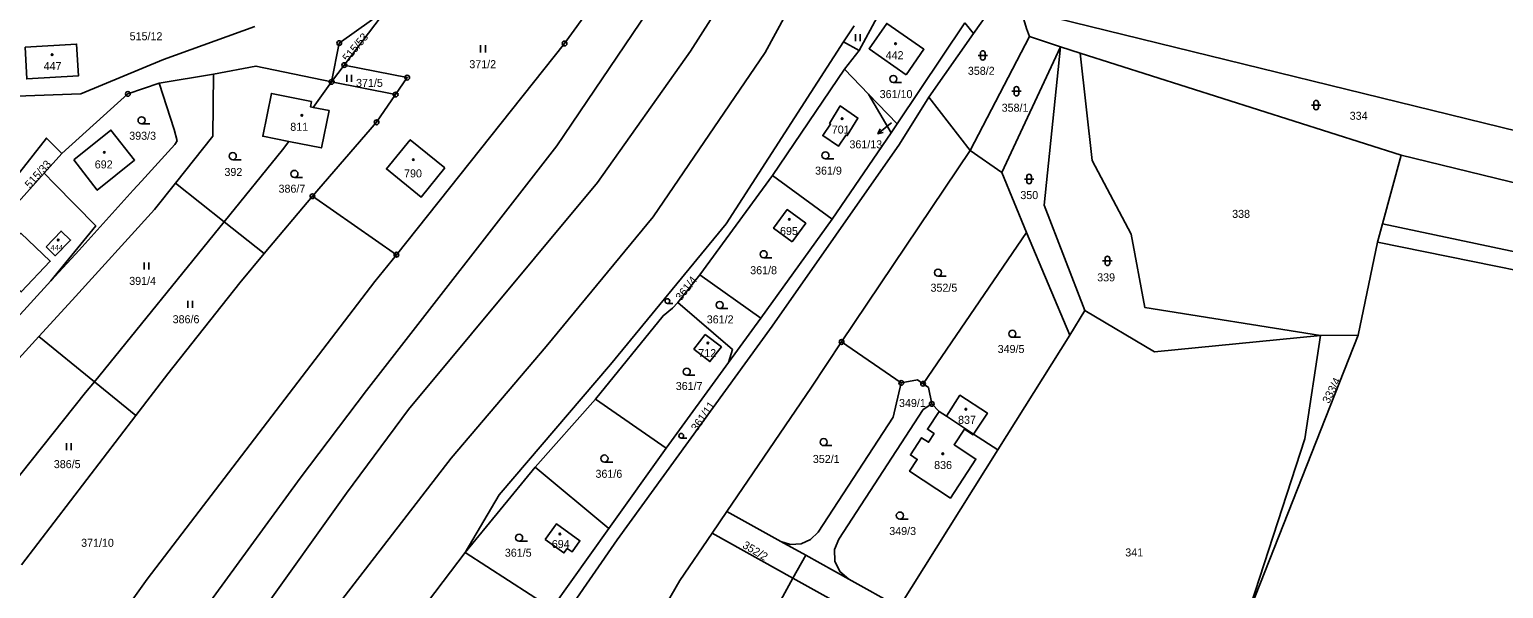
# Model space of a CAD drawing. Extents: x -725728 to -720881, y -1068679 to -1063504.
# Drawn here: x -722498.2 to -722185.2, y -1065489.8 to -1065371.2 of the extents above; entities that cross this region are included whole.
import ezdxf

# ---------------------------------------------------------------- set-up
doc = ezdxf.new("R2010")
doc.units = 0
for name, color, linetype in [('Hranice parcel', 7, 'Continuous'), ('Parcelní čísla', 7, 'Continuous'), ('Pop  PČ popisy', 7, 'Continuous'), ('Značky bodu BP', 7, 'Continuous'), ('Značky budov', 7, 'Continuous'), ('Značky kultur', 7, 'Continuous')]:
    doc.layers.add(name, color=color, linetype=linetype)

# ---------------------------------------------------------------- blocks, each defined once
blk = doc.blocks.new('4.02_4')
at = {"layer": 'Značky budov'}
blk.add_circle((-0.001, 0), 0.0175, dxfattribs=at)
blk = doc.blocks.new('4.02_3')
at = {"layer": 'Značky budov'}
blk.add_circle((-0.001, 0), 0.0175, dxfattribs=at)
blk = doc.blocks.new('1029_162')
at = {"layer": 'Pop  PČ popisy'}
for p, q in [((0, 0), (-0.233, -0.189)), ((-0.233, -0.189), (-0.187, -0.087)), ((-0.233, -0.189), (-0.124, -0.165))]:
    blk.add_line(p, q, dxfattribs=at)
blk = doc.blocks.new('3.04_2')
at = {"layer": 'Značky kultur'}
blk.add_line((0.001, 0), (0.176, 0), dxfattribs=at)
blk.add_circle((0.001, 0.075), 0.075, dxfattribs=at)
blk = doc.blocks.new('3.06_2')
at = {"layer": 'Značky kultur'}
for p, q in [((-0.051, 0), (-0.051, 0.15)), ((0.049, 0), (0.049, 0.15))]:
    blk.add_line(p, q, dxfattribs=at)
blk = doc.blocks.new('3.06_1')
at = {"layer": 'Značky kultur'}
for p, q in [((-0.051, 0), (-0.051, 0.15)), ((0.049, 0), (0.049, 0.15))]:
    blk.add_line(p, q, dxfattribs=at)
blk = doc.blocks.new('3.04_4')
at = {"layer": 'Značky kultur'}
blk.add_line((0, 0), (0.118, 0), dxfattribs=at)
blk.add_circle((0, 0.05), 0.0502, dxfattribs=at)
blk = doc.blocks.new('3.04_3')
at = {"layer": 'Značky kultur'}
blk.add_line((0.001, 0), (0.176, 0), dxfattribs=at)
blk.add_circle((0.001, 0.075), 0.075, dxfattribs=at)
blk = doc.blocks.new('3.16_2')
at = {"layer": 'Značky kultur'}
for p, q in [((-0.1, 0.1), (0.1, 0.1)), ((-0.05, 0.15), (-0.05, 0.05)), ((0.05, 0.05), (0.05, 0.15))]:
    blk.add_line(p, q, dxfattribs=at)
for centre, start, end in [((0, 0.15), 0, 180), ((0, 0.05), 180, 359.9879)]:
    blk.add_arc(centre, 0.05, start, end, dxfattribs=at)
blk = doc.blocks.new('3.16_3')
at = {"layer": 'Značky kultur'}
for p, q in [((-0.1, 0.1), (0.1, 0.1)), ((-0.05, 0.15), (-0.05, 0.05)), ((0.05, 0.05), (0.05, 0.15))]:
    blk.add_line(p, q, dxfattribs=at)
for centre, start, end in [((0, 0.15), 0, 180), ((0, 0.05), 180, 359.9879)]:
    blk.add_arc(centre, 0.05, start, end, dxfattribs=at)
blk = doc.blocks.new('3.04_5')
at = {"layer": 'Značky kultur'}
blk.add_line((0, 0), (0.118, 0), dxfattribs=at)
blk.add_circle((0, 0.05), 0.0502, dxfattribs=at)
blk = doc.blocks.new('1.05_1')
at = {"layer": 'Značky bodu BP'}
for radius in [0.05, 0.00303]:
    blk.add_circle((0, 0), radius, dxfattribs=at)
blk = doc.blocks.new('1.05_2')
at = {"layer": 'Značky bodu BP'}
for radius in [0.05, 0.00303]:
    blk.add_circle((0, 0), radius, dxfattribs=at)

msp = doc.modelspace()

# ---------------------------------------------------------------- linework, layer by layer
at = {"layer": 'Hranice parcel'}
for p, q in [((-722322.02, -1065375.63), (-722313.53, -1065359.88)), ((-722297.73, -1065372.01), (-722289.71, -1065360.63)), ((-722422.39, -1065366.92), (-722431.35, -1065378.72)), ((-722323.1, -1065370.39), (-722325.33, -1065373.76)), ((-722313.95, -1065391.21), (-722299.57, -1065369.73)), ((-722299.57, -1065369.73), (-722297.73, -1065372.01)), ((-722297.73, -1065372.01), (-722307.21, -1065385.49)), ((-722285.87, -1065372.62), (-722298.44, -1065396.81)), ((-722285.87, -1065372.62), (-722279.22, -1065374.83)), ((-722325.33, -1065373.76), (-722322.02, -1065375.63)), ((-722325.15, -1065379.57), (-722322.02, -1065375.63)), ((-722279.22, -1065374.83), (-722291.7, -1065401.51)), ((-722279.22, -1065374.83), (-722275.08, -1065376.15)), ((-722275.08, -1065376.15), (-722206.94, -1065397.81)), ((-722434.04, -1065382.27), (-722431.35, -1065378.72)), ((-722340.44, -1065402.15), (-722325.15, -1065379.57)), ((-722320.06, -1065384.86), (-722325.15, -1065379.57)), ((-722470.69, -1065382.58), (-722477.31, -1065384.82)), ((-722470.69, -1065382.58), (-722459.11, -1065380.63)), ((-722437.96, -1065387.68), (-722434.04, -1065382.27)), ((-722434.04, -1065382.27), (-722420.45, -1065384.96)), ((-722477.31, -1065384.82), (-722491.32, -1065397.48)), ((-722315.21, -1065393.09), (-722320.06, -1065384.86)), ((-722320.06, -1065384.86), (-722313.95, -1065391.21)), ((-722298.44, -1065396.81), (-722307.21, -1065385.49)), ((-722315.21, -1065393.09), (-722313.95, -1065391.21)), ((-722327.76, -1065411.4), (-722315.21, -1065393.09)), ((-722491.32, -1065397.48), (-722495.09, -1065401.67)), ((-722325.75, -1065437.48), (-722298.44, -1065396.81)), ((-722291.7, -1065401.51), (-722298.44, -1065396.81)), ((-722206.94, -1065397.81), (-722210.88, -1065412.37)), ((-722163.36, -1065408.44), (-722206.94, -1065397.81)), ((-722291.7, -1065401.51), (-722286.47, -1065414.22)), ((-722467.23, -1065403.77), (-722456.87, -1065411.99)), ((-722355.87, -1065423.25), (-722340.44, -1065402.15)), ((-722327.76, -1065411.4), (-722340.44, -1065402.15)), ((-722438.14, -1065406.56), (-722448.4, -1065418.72)), ((-722438.14, -1065406.56), (-722420.29, -1065418.95)), ((-722456.87, -1065411.99), (-722484.43, -1065445.91)), ((-722448.4, -1065418.72), (-722456.87, -1065411.99)), ((-722342.93, -1065432.39), (-722327.76, -1065411.4)), ((-722286.47, -1065414.22), (-722308.45, -1065446.33)), ((-722286.47, -1065414.22), (-722277.28, -1065436.06)), ((-722210.88, -1065412.37), (-722211.93, -1065416.27)), ((-722211.93, -1065416.27), (-722216.02, -1065436.03)), ((-722360.55, -1065429.09), (-722355.87, -1065423.25)), ((-722355.87, -1065423.25), (-722342.93, -1065432.39)), ((-722349.73, -1065441.8), (-722342.93, -1065432.39)), ((-722277.28, -1065436.06), (-722274.06, -1065430.83)), ((-722292.57, -1065460.38), (-722277.28, -1065436.06)), ((-722239.79, -1065496.32), (-722216.02, -1065436.03)), ((-722216.02, -1065436.03), (-722224.06, -1065436.13)), ((-722484.43, -1065445.91), (-722496.21, -1065436.34)), ((-722313.07, -1065446.17), (-722325.75, -1065437.48)), ((-722363, -1065460.03), (-722349.73, -1065441.8)), ((-722475.62, -1065453.06), (-722484.43, -1065445.91)), ((-722390.84, -1065464.04), (-722378.04, -1065449.6)), ((-722378.04, -1065449.6), (-722363, -1065460.03)), ((-722305.03, -1065452.2), (-722306.59, -1065450.62)), ((-722475.62, -1065453.06), (-722499.9, -1065484.77)), ((-722305.03, -1065452.2), (-722303.5, -1065453.21)), ((-722297.71, -1065457.02), (-722303.5, -1065453.21)), ((-722292.57, -1065460.38), (-722297.71, -1065457.02)), ((-722375.21, -1065477.05), (-722363, -1065460.03)), ((-722313.55, -1065493.79), (-722292.57, -1065460.38)), ((-722405.71, -1065482.16), (-722390.84, -1065464.04)), ((-722375.21, -1065477.05), (-722390.84, -1065464.04)), ((-722353.26, -1065478.03), (-722350.13, -1065473.45)), ((-722350.13, -1065473.45), (-722338.68, -1065479.8)), ((-722387.28, -1065494.04), (-722375.21, -1065477.05)), ((-722360.13, -1065488.13), (-722353.26, -1065478.03)), ((-722353.26, -1065478.03), (-722336.09, -1065487.59)), ((-722338.68, -1065479.8), (-722333.37, -1065482.74)), ((-722405.71, -1065482.16), (-722437.07, -1065523.51)), ((-722387.28, -1065494.04), (-722405.71, -1065482.16)), ((-722333.37, -1065482.74), (-722336.09, -1065487.59)), ((-722333.37, -1065482.74), (-722324.21, -1065487.82)), ((-722388.93, -1065538.03), (-722360.13, -1065488.13)), ((-722336.09, -1065487.59), (-722349.74, -1065512.51)), ((-722320.65, -1065496.14), (-722336.09, -1065487.59)), ((-722324.21, -1065487.82), (-722313.55, -1065493.79))]:
    msp.add_line(p, q, dxfattribs=at)
for points in [[(-722420.29, -1065418.95), (-722384.59, -1065374.13), (-722365.18, -1065347.29)], [(-722357.52, -1065354), (-722366.97, -1065367.42), (-722386.23, -1065395.85), (-722426.63, -1065447.77), (-722440.7, -1065466.38), (-722459.23, -1065491.7), (-722491.34, -1065537.79), (-722505.02, -1065562.62), (-722515.04, -1065584.73)], [(-722509.49, -1065656.03), (-722505.95, -1065643.48), (-722499.31, -1065618.25), (-722493.82, -1065602.22), (-722476.6, -1065559.87), (-722470.13, -1065549), (-722458.19, -1065529.41), (-722435.46, -1065496.86), (-722408.64, -1065462.11), (-722388.47, -1065438.41), (-722365.73, -1065410.93), (-722342.01, -1065376.02), (-722333.62, -1065360.61)], [(-722348.82, -1065361.62), (-722357.82, -1065375.76), (-722377.6, -1065403.63), (-722417.73, -1065451.78), (-722430.87, -1065469.56), (-722449.11, -1065495.01), (-722482.56, -1065541.98), (-722499.31, -1065573.36), (-722510.08, -1065599.54), (-722518.29, -1065629.02), (-722520.91, -1065639.92), (-722526.78, -1065669.58)], [(-722434.04, -1065382.27), (-722432.42, -1065374.03), (-722422.39, -1065366.92)], [(-722163.36, -1065408.44), (-722167.52, -1065396.33), (-722287.65, -1065366.89)], [(-722287.65, -1065366.89), (-722286.48, -1065370.94), (-722285.87, -1065372.62)], [(-722312.04, -1065380.76), (-722319.92, -1065375.23), (-722316.15, -1065369.86), (-722308.27, -1065375.36), (-722312.04, -1065380.76)], [(-722450.38, -1065370.51), (-722469.75, -1065377.56), (-722487.29, -1065384.79), (-722501, -1065385.31)], [(-722499.16, -1065374.89), (-722488.21, -1065374.27), (-722487.84, -1065381.01), (-722498.78, -1065381.63), (-722499.16, -1065374.89)], [(-722325.33, -1065373.76), (-722350.28, -1065412.41), (-722374.83, -1065442.25), (-722398.47, -1065469.89), (-722405.71, -1065482.16)], [(-722274.06, -1065430.83), (-722282.75, -1065408.43), (-722279.22, -1065374.83)], [(-722275.08, -1065376.15), (-722272.55, -1065398.98), (-722264.24, -1065414.61), (-722261.34, -1065430.17), (-722224.06, -1065436.13)], [(-722459.11, -1065380.63), (-722450.11, -1065378.94), (-722434.04, -1065382.27)], [(-722431.35, -1065378.72), (-722417.99, -1065381.38), (-722420.45, -1065384.96)], [(-722493.65, -1065424.47), (-722487.63, -1065417.98), (-722476.18, -1065405.24), (-722474.41, -1065403.36), (-722467.38, -1065395.58), (-722466.83, -1065394.8), (-722467.47, -1065392.36), (-722470.69, -1065382.58)], [(-722459.11, -1065380.63), (-722459.31, -1065393.83), (-722467.23, -1065403.77)], [(-722443.12, -1065394.91), (-722448.68, -1065393.8), (-722446.85, -1065384.72), (-722438.35, -1065386.44), (-722438.55, -1065387.56), (-722437.96, -1065387.68)], [(-722420.45, -1065384.96), (-722424.5, -1065390.86), (-722438.14, -1065406.56)], [(-722307.21, -1065385.49), (-722313.43, -1065395.51), (-722340.48, -1065434.13), (-722373.38, -1065479.46), (-722383.26, -1065493.66), (-722384.76, -1065495.67)], [(-722437.96, -1065387.68), (-722434.6, -1065388.35), (-722436.21, -1065396.3), (-722443.12, -1065394.91)], [(-722324.76, -1065393.53), (-722326.42, -1065395.95), (-722329.75, -1065393.67), (-722328.08, -1065391.23), (-722328.3, -1065391.09), (-722326.02, -1065387.38), (-722322.27, -1065389.95), (-722324.55, -1065393.68), (-722324.76, -1065393.53)], [(-722503.1, -1065405.07), (-722494.62, -1065394.19), (-722491.32, -1065397.48)], [(-722488.8, -1065398.82), (-722480.93, -1065392.5), (-722475.88, -1065398.87), (-722483.83, -1065405.29), (-722488.8, -1065398.82)], [(-722456.87, -1065411.99), (-722444.48, -1065396.71), (-722443.12, -1065394.91)], [(-722409.98, -1065400.55), (-722415.05, -1065406.75), (-722422.42, -1065400.75), (-722417.34, -1065394.54), (-722409.98, -1065400.55)], [(-722495.09, -1065401.67), (-722500.6, -1065407.78), (-722503.1, -1065405.07)], [(-722493.65, -1065424.47), (-722484.15, -1065412.82), (-722492.88, -1065403.9), (-722495.09, -1065401.67)], [(-722496.21, -1065436.34), (-722489.14, -1065428.59), (-722471.65, -1065409.33), (-722467.23, -1065403.77)], [(-722336.23, -1065416.23), (-722340.19, -1065413.34), (-722337.3, -1065409.39), (-722333.35, -1065412.27), (-722336.23, -1065416.23)], [(-722500.74, -1065415.13), (-722500.05, -1065414.4), (-722493.79, -1065420.34), (-722499.97, -1065426.85), (-722506.33, -1065421.02), (-722504.6, -1065419.2), (-722505.62, -1065418.23), (-722504.34, -1065416.89), (-722504.6, -1065416.65), (-722502.01, -1065413.92), (-722500.74, -1065415.13)], [(-722494.67, -1065417.29), (-722491.49, -1065413.93), (-722489.5, -1065415.86), (-722492.73, -1065419.18), (-722494.67, -1065417.29)], [(-722210.88, -1065412.37), (-722156.68, -1065423.86), (-722129.68, -1065414.44)], [(-722211.93, -1065416.27), (-722156.77, -1065427.49), (-722142.01, -1065422.5), (-722129.68, -1065414.44)], [(-722513.8, -1065551.72), (-722499.78, -1065524.95), (-722473.24, -1065487.78), (-722424.84, -1065424.64), (-722420.29, -1065418.95)], [(-722448.4, -1065418.72), (-722453.55, -1065424.92), (-722468.85, -1065444.21), (-722475.62, -1065453.06)], [(-722554.78, -1065489.69), (-722519.73, -1065453.04), (-722493.65, -1065424.47)], [(-722378.04, -1065449.6), (-722363.65, -1065431.9), (-722361.68, -1065430.28), (-722360.55, -1065429.09)], [(-722349.73, -1065441.8), (-722348.89, -1065439.09), (-722360.55, -1065429.09)], [(-722274.06, -1065430.83), (-722259.26, -1065439.59), (-722224.06, -1065436.13)], [(-722354.71, -1065435.89), (-722357.12, -1065438.99), (-722353.7, -1065441.64), (-722351.27, -1065438.51), (-722354.71, -1065435.89)], [(-722224.06, -1065436.13), (-722227.38, -1065458.03), (-722239.79, -1065496.32)], [(-722523.59, -1065465.92), (-722515.32, -1065457.26), (-722496.21, -1065436.34)], [(-722350.13, -1065473.45), (-722332.16, -1065447.04), (-722325.75, -1065437.48)], [(-722484.43, -1065445.91), (-722486.33, -1065448.23), (-722509.45, -1065477.18)], [(-722313.07, -1065446.17), (-722314.81, -1065453.42), (-722330.74, -1065477.83), (-722332.32, -1065479.4), (-722334.35, -1065480.33), (-722336.58, -1065480.45), (-722338.68, -1065479.8)], [(-722308.45, -1065446.33), (-722309.62, -1065445.53), (-722313.07, -1065446.17)], [(-722306.59, -1065450.62), (-722307.27, -1065447.14), (-722308.45, -1065446.33)], [(-722324.21, -1065487.82), (-722326.1, -1065486.19), (-722327.16, -1065483.99), (-722327.25, -1065481.54), (-722326.32, -1065479.29), (-722308.4, -1065451.83), (-722306.59, -1065450.62)], [(-722303.5, -1065453.21), (-722300.6, -1065448.77), (-722294.79, -1065452.57), (-722297.71, -1065457.02)], [(-722297.71, -1065457.02), (-722297.82, -1065457.19), (-722299.67, -1065455.97), (-722301.85, -1065459.3), (-722297.22, -1065462.34), (-722302.64, -1065470.6), (-722311.31, -1065464.91), (-722309.67, -1065462.4), (-722311.14, -1065461.44), (-722308.75, -1065457.79), (-722307.28, -1065458.75), (-722306.09, -1065456.92), (-722307.51, -1065455.99), (-722305.03, -1065452.2)], [(-722388.67, -1065479.43), (-722384.7, -1065482.25), (-722384.02, -1065481.3), (-722382.99, -1065482.03), (-722381.3, -1065479.65), (-722386.3, -1065476.1), (-722388.67, -1065479.43)]]:
    msp.add_lwpolyline(points, dxfattribs=at)
at = {"layer": 'Pop  PČ popisy'}
msp.add_line((-722315.16, -1065390.95), (-722315.71, -1065391.39), dxfattribs=at)

# ---------------------------------------------------------------- block references
at = {"layer": 'Pop  PČ popisy', "xscale": 10, "yscale": 10}
msp.add_blockref('1029_162', (-722315.71, -1065391.39), dxfattribs=at)
at = {"layer": 'Značky bodu BP', "xscale": 10, "yscale": 10}
for name, p in [('1.05_1', (-722432.42, -1065374.03)), ('1.05_2', (-722384.59, -1065374.13)), ('1.05_1', (-722431.35, -1065378.72)), ('1.05_1', (-722434.04, -1065382.27)), ('1.05_2', (-722417.99, -1065381.38)), ('1.05_1', (-722477.31, -1065384.82)), ('1.05_1', (-722420.45, -1065384.96)), ('1.05_1', (-722424.5, -1065390.86)), ('1.05_1', (-722438.14, -1065406.56)), ('1.05_1', (-722420.29, -1065418.95)), ('1.05_1', (-722325.75, -1065437.48)), ('1.05_2', (-722313.07, -1065446.17)), ('1.05_1', (-722308.45, -1065446.33)), ('1.05_1', (-722306.59, -1065450.62))]:
    msp.add_blockref(name, p, dxfattribs=at)
at = {"layer": 'Značky budov', "xscale": 10, "yscale": 10}
for name, p in [('4.02_3', (-722493.4, -1065376.49)), ('4.02_4', (-722314.28, -1065374.18)), ('4.02_4', (-722440.35, -1065389.39)), ('4.02_3', (-722325.63, -1065390.07)), ('4.02_3', (-722482.32, -1065397.23)), ('4.02_3', (-722416.69, -1065398.77)), ('4.02_3', (-722336.84, -1065411.45)), ('4.02_3', (-722492.11, -1065415.84)), ('4.02_3', (-722354.13, -1065437.71)), ('4.02_3', (-722299.35, -1065451.75)), ('4.02_3', (-722304.25, -1065461.2)), ('4.02_3', (-722385.57, -1065478.22))]:
    msp.add_blockref(name, p, dxfattribs=at)
at = {"layer": 'Značky kultur', "xscale": 10, "yscale": 10}
for name, p in [('3.06_2', (-722322.28, -1065373.66)), ('3.06_1', (-722401.89, -1065376.01)), ('3.16_3', (-722295.77, -1065377.67)), ('3.06_1', (-722430.31, -1065382.29)), ('3.04_3', (-722314.77, -1065382.4)), ('3.16_2', (-722288.6, -1065385.27)), ('3.16_2', (-722224.96, -1065388.2)), ('3.04_2', (-722474.42, -1065391.19)), ('3.04_2', (-722455.05, -1065398.79)), ('3.04_3', (-722329.18, -1065398.63)), ('3.04_2', (-722441.96, -1065402.55)), ('3.16_3', (-722285.92, -1065403.89)), ('3.04_2', (-722342.3, -1065419.6)), ('3.16_2', (-722269.3, -1065421.28)), ('3.06_1', (-722473.35, -1065422.12)), ('3.04_2', (-722305.28, -1065423.51)), ('3.06_1', (-722464.09, -1065430.23)), ('3.04_4', (-722362.73, -1065429.31)), ('3.04_2', (-722351.65, -1065430.37)), ('3.04_2', (-722289.48, -1065436.48)), ('3.04_2', (-722358.64, -1065444.54)), ('3.04_5', (-722359.79, -1065457.88)), ('3.04_2', (-722329.56, -1065459.47)), ('3.06_1', (-722489.83, -1065460.47)), ('3.04_2', (-722376.11, -1065462.96)), ('3.04_2', (-722313.38, -1065475.06)), ('3.04_2', (-722394.24, -1065479.77))]:
    msp.add_blockref(name, p, dxfattribs=at)

# ---------------------------------------------------------------- texts
at = {"layer": 'Parcelní čísla'}
for s, height, p in [('515/12', 1.7, (-722476.94, -1065373.44)), ('442', 1.7, (-722316.38, -1065377.46)), ('447', 1.7, (-722495.21, -1065379.77)), ('371/2', 1.7, (-722404.8, -1065379.37)), ('358/2', 1.7, (-722298.93, -1065380.78)), ('371/5', 1.7, (-722428.86, -1065383.34)), ('361/10', 1.7, (-722317.66, -1065385.72)), ('358/1', 1.7, (-722291.75, -1065388.61)), ('334', 1.7, (-722217.84, -1065390.32)), ('811', 1.7, (-722442.83, -1065392.66)), ('701', 1.7, (-722327.83, -1065393.24)), ('393/3', 1.7, (-722477.03, -1065394.56)), ('361/13', 1.7, (-722324.08, -1065396.38)), ('692', 1.7, (-722484.35, -1065400.64)), ('392', 1.7, (-722456.81, -1065402.24)), ('790', 1.7, (-722418.66, -1065402.55)), ('361/9', 1.7, (-722331.38, -1065401.96)), ('386/7', 1.7, (-722445.32, -1065405.79)), ('350', 1.7, (-722287.78, -1065407.15)), ('338', 1.7, (-722242.8, -1065411.14)), ('695', 1.7, (-722338.82, -1065414.77)), ('444', 1.14, (-722493.74, -1065418.02)), ('391/4', 1.7, (-722477.03, -1065425.36)), ('361/8', 1.7, (-722345.15, -1065423.1)), ('339', 1.7, (-722271.46, -1065424.61)), ('352/5', 1.7, (-722306.86, -1065426.81)), ('386/6', 1.7, (-722467.81, -1065433.5)), ('361/2', 1.7, (-722354.38, -1065433.53)), ('712', 1.7, (-722356.18, -1065440.69)), ('349/5', 1.7, (-722292.6, -1065439.81)), ('361/7', 1.7, (-722360.96, -1065447.67)), ('349/1', 1.7, (-722313.55, -1065451.28)), ('837', 1.7, (-722301.01, -1065454.85)), ('386/5', 1.7, (-722493.05, -1065464.25)), ('352/1', 1.7, (-722331.85, -1065463.15)), ('836', 1.7, (-722306.09, -1065464.44)), ('361/6', 1.7, (-722378.01, -1065466.3)), ('349/3', 1.7, (-722315.62, -1065478.45)), ('371/10', 1.7, (-722487.25, -1065480.95)), ('694', 1.7, (-722387.29, -1065481.2)), ('361/5', 1.7, (-722397.26, -1065483.05)), ('341', 1.7, (-722265.5, -1065482.99))]:
    msp.add_text(s, height=height, dxfattribs=at).set_placement(p)
for s, rotation, p in [('515/53', 50, (-722430.62, -1065378.14)), ('515/33', 48, (-722498.11, -1065405.01)), ('361/4', 52, (-722359.84, -1065428.85)), ('333/4', 63, (-722222.24, -1065450.67)), ('361/11', 55, (-722356.48, -1065456.57)), ('352/2', 329, (-722346.95, -1065481.04))]:
    msp.add_text(s, height=1.7, rotation=rotation, dxfattribs=at).set_placement(p)

doc.saveas('drawing.dxf')
